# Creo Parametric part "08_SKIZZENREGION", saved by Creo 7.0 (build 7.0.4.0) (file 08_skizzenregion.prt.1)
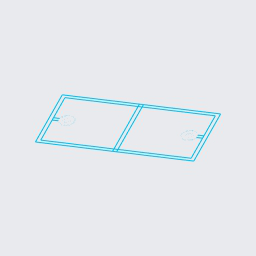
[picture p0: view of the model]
Units: millimeter Kilogram Sec (mmKs); MM, KILOGRAM, SECS
Materials in the file: S235JRG2

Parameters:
  PTC_MATERIAL_NAME = "S235JRG2"
  BENENNUNG = "XXX"
  DATUM = "XX.XX.XX"
  ERSTELLER = "ARINDA"
  TEILETYP = "Fertigungsteil"
  SELECT_EN_NAME = "S235JRG2"
  SELECT_DIN_NAME = "RSt37-2"
  SELECT_DIN_NUMBER = "1.0038"
  SELECT_ASTM_NAME = "A 283 M Grade 2"
  MATERIAL_GROUP = "ME_ST_Baustahl"
  STANDARD_EN_DELIVERYSPEC = "DIN EN 10025"
  STANDARD_DIN_DELIVERYSPEC = "DIN 17100"

Other parameters: MASSE

Created from: ARINDA-STARTTEIL.PRT

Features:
  1. coordinate system "CS0"
  2. datum plane "DTM1", "T_RECHTS_Y-Z"
  3. datum plane "DTM2", "T_OBEN_X-Z"
  4. datum plane "DTM3", "T_VORNE_X-Y"
  5. datum axis "T_X-ACHSE"
  6. datum axis "A_1"
  7. datum axis "A_2"
  8. sketch "Skizze 1"
  9. sketch "Skizze 2"
  10. sketch "Skizze 3"
  11. sketch "Skizze 4"

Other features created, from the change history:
  extrusion "Profil 1"
  extrusion "Profil 2"
  extrusion "Profil 3"
  extruded cut "Profil 4"
  extrusion "Profil 5"

Other named items: T_BASIC, BODEN-WAND, DOM, STEG, RIPPE, T_Y-ACHSE, T_Z-ACHSE

Layers: 00_STD-ACHSEN, 00_STD-EBENEN, 00_STD-KOORDSYS, 01_KURVEN, KURVENELEMENTE, VOLUMENGEOMETRIE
